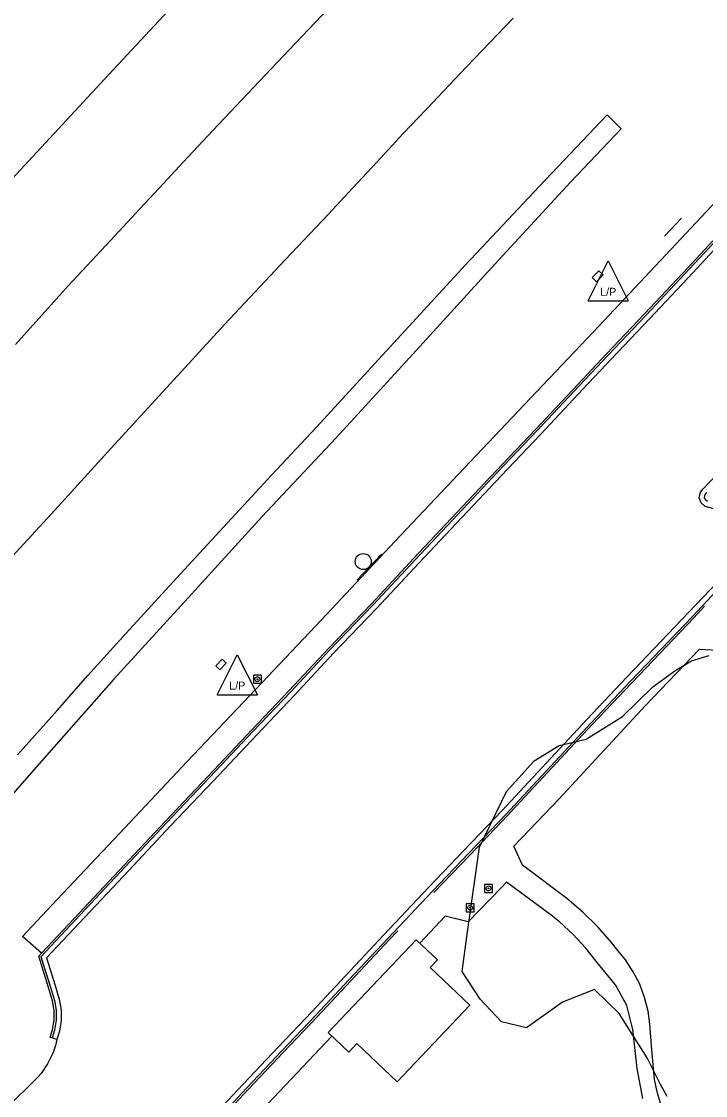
# Model space of a CAD drawing. Extents: x 2161152 to 2175754, y 602179 to 617749.
# Drawn here: x 2163221.4 to 2163392.2, y 605136.2 to 605404.6 of the extents above; entities that cross this region are included whole.
import ezdxf

# ---------------------------------------------------------------- set-up
doc = ezdxf.new("R2010")
doc.units = 0
for name, color, linetype in [('RD_EX_Bldg', 7, 'Continuous'), ('RD_EX_BldgApp_Sign', 7, 'Continuous'), ('RD_EX_Conc_Curb', 7, 'Continuous'), ('RD_EX_Conc_Gutter', 7, 'Continuous'), ('RD_EX_Conc_Sidewalk', 7, 'Continuous'), ('RD_EX_DR_Paved_Drainage', 7, 'Continuous'), ('RD_EX_Fence_Other', 7, 'Continuous'), ('RD_EX_Misc', 7, 'Continuous'), ('RD_EX_Parking_Conc', 7, 'Continuous'), ('RD_EX_Road', 7, 'Continuous'), ('RD_EX_UT', 7, 'Continuous'), ('RD_EX_VEG', 7, 'Continuous')]:
    doc.layers.add(name, color=color, linetype=linetype)

msp = doc.modelspace()

# ---------------------------------------------------------------- linework, layer by layer
at = {"layer": 'RD_EX_Bldg'}
msp.add_lwpolyline([(2163297.98, 605151.89), (2163319.97, 605175.07), (2163325.25, 605170.05), (2163323.43, 605168.13), (2163333.36, 605158.71), (2163315.2, 605139.58), (2163305.14, 605149.12), (2163303.13, 605147), (2163297.98, 605151.89)], dxfattribs=at)
at = {"layer": 'RD_EX_BldgApp_Sign'}
for p, q in [((2163381.98, 605350.93), (2163386.24, 605355.48)), ((2163305.09, 605264.94), (2163311.27, 605271.48))]:
    msp.add_line(p, q, dxfattribs=at)
msp.add_circle((2163306.72, 605269.61), 2, dxfattribs=at)
at = {"layer": 'RD_EX_Conc_Curb'}
for points in [[(2163229.01, 605150.55), (2163228.87, 605150.59), (2163228.53, 605150.69), (2163229.12, 605152.63), (2163229.49, 605155.02), (2163229.48, 605157.44), (2163229.09, 605159.83), (2163228.09, 605163.12), (2163225.64, 605170.99), (2163226.34, 605171.74), (2163234.47, 605180.44), (2163246.88, 605193.63), (2163257.31, 605204.74), (2163267.94, 605215.95), (2163278.89, 605227.55), (2163288.25, 605237.42), (2163298.02, 605247.88), (2163308.77, 605259.08), (2163319.33, 605270.43), (2163328.67, 605280.34), (2163339.88, 605292.28), (2163349.8, 605302.68), (2163360.29, 605313.86), (2163367.5, 605321.55), (2163376.98, 605331.51), (2163387.79, 605343), (2163394.05, 605349.81)], [(2163394.42, 605349.47), (2163388.16, 605342.66), (2163377.34, 605331.17), (2163367.87, 605321.21), (2163360.66, 605313.52), (2163350.16, 605302.34), (2163340.24, 605291.93), (2163329.03, 605280), (2163319.7, 605270.09), (2163309.13, 605258.73), (2163298.39, 605247.53), (2163288.61, 605237.08), (2163279.25, 605227.21), (2163268.3, 605215.61), (2163257.67, 605204.4), (2163247.24, 605193.29), (2163234.83, 605180.1), (2163226.21, 605170.86), (2163228.57, 605163.26), (2163229.58, 605159.94), (2163229.98, 605157.48), (2163229.99, 605154.98), (2163229.61, 605152.51), (2163229.01, 605150.55)], [(2163392.72, 605284.6), (2163392.19, 605285.04), (2163391.98, 605285.64), (2163392.12, 605286.38), (2163392.55, 605286.9)], [(2163269.71, 605129.54), (2163277.67, 605138.1), (2163286.4, 605147.32), (2163294.81, 605156.16), (2163304.38, 605166.38), (2163312.86, 605175.37), (2163324.02, 605187.24), (2163333.02, 605196.63), (2163342.29, 605206.39), (2163363.57, 605229.26), (2163373.5, 605239.75), (2163388.92, 605255.92), (2163396.02, 605263.49)], [(2163324.38, 605186.89), (2163333.38, 605196.29), (2163342.66, 605206.05), (2163363.93, 605228.92), (2163373.86, 605239.41), (2163389.28, 605255.57), (2163391.91, 605258.49)], [(2163315.38, 605177.34), (2163313.22, 605175.03), (2163304.74, 605166.04), (2163295.17, 605155.82), (2163286.76, 605146.98), (2163278.03, 605137.76), (2163269.88, 605128.99)]]:
    msp.add_lwpolyline(points, dxfattribs=at)
at = {"layer": 'RD_EX_Conc_Gutter'}
for points in [[(2163395.33, 605348.62), (2163389.07, 605341.81), (2163378.25, 605330.31), (2163368.77, 605320.35), (2163361.57, 605312.67), (2163351.07, 605301.48), (2163341.15, 605291.08), (2163329.94, 605279.15), (2163320.61, 605269.24), (2163310.04, 605257.88), (2163299.29, 605246.68), (2163289.52, 605236.22), (2163280.16, 605226.35), (2163269.21, 605214.75), (2163258.58, 605203.54), (2163248.15, 605192.44), (2163235.74, 605179.24), (2163227.61, 605170.54), (2163229.76, 605163.63), (2163230.8, 605160.22), (2163231.23, 605157.58), (2163231.24, 605154.89), (2163230.83, 605152.23), (2163230.2, 605150.18), (2163229.01, 605150.55)], [(2163395.86, 605282.4), (2163392.11, 605283.42), (2163391.08, 605284.27), (2163390.64, 605285.55), (2163390.91, 605286.95), (2163391.59, 605287.76), (2163395.27, 605291.63)], [(2163269.26, 605131), (2163276.7, 605139.01), (2163285.44, 605148.23), (2163293.85, 605157.07), (2163303.41, 605167.29), (2163311.89, 605176.28), (2163323.04, 605188.18), (2163332.04, 605197.57), (2163341.31, 605207.32), (2163362.58, 605230.18), (2163372.52, 605240.69), (2163387.94, 605256.85), (2163395.08, 605264.38)]]:
    msp.add_lwpolyline(points, dxfattribs=at)
at = {"layer": 'RD_EX_Conc_Sidewalk'}
for points in [[(2163226.34, 605171.74), (2163221.57, 605175.92), (2163230.15, 605185.03), (2163245.81, 605201.68), (2163262.77, 605219.63), (2163278.37, 605236.12), (2163296.31, 605255.09), (2163314.63, 605274.67), (2163331.93, 605292.95), (2163348.43, 605310.39), (2163364.19, 605327.05), (2163383.51, 605347.58), (2163401.3, 605366.52), (2163420.93, 605387.17), (2163438.78, 605406.02)], [(2163381.24, 605133.39), (2163380.18, 605136.72), (2163379.49, 605140.15), (2163378.77, 605147.55), (2163378.29, 605154.02), (2163377.84, 605157.24), (2163376.99, 605160.66), (2163375.76, 605163.96), (2163374.16, 605167.11), (2163372.23, 605170.07), (2163369.97, 605172.79), (2163368.71, 605174.39), (2163365.27, 605178.31), (2163361.54, 605181.97), (2163357.54, 605185.36), (2163346.47, 605193.74), (2163344.31, 605198.49), (2163355.61, 605210.33), (2163377.14, 605233.53), (2163390.72, 605247.73), (2163396.8, 605247.38)], [(2163376.58, 605135.41), (2163375.17, 605142.89), (2163374.08, 605152.67), (2163372.57, 605158.66), (2163369.74, 605163.81), (2163365.14, 605169.37), (2163362.27, 605173.02), (2163359.13, 605176.43), (2163355.73, 605179.56), (2163353.67, 605181.23), (2163342.51, 605189.48), (2163341.24, 605188.17), (2163332.9, 605179.55), (2163327.15, 605180.95), (2163320.84, 605174.25)], [(2163298.9, 605151.01), (2163282.84, 605134.04)]]:
    msp.add_lwpolyline(points, dxfattribs=at)
at = {"layer": 'RD_EX_DR_Paved_Drainage'}
msp.add_lwpolyline([(2163220.36, 605221.3), (2163230.27, 605232.43), (2163237.96, 605241.17), (2163247.47, 605251.68), (2163259.14, 605264.44), (2163268.82, 605274.98), (2163283.92, 605291.33), (2163294.95, 605303.12), (2163312.4, 605322.22), (2163332.22, 605343.79), (2163350.7, 605363.42), (2163367.62, 605381.24), (2163368.71, 605380.19), (2163370.25, 605378.69), (2163371.17, 605377.81), (2163358.45, 605364.42), (2163339.57, 605343.99), (2163319.12, 605321.49), (2163299.87, 605300.45), (2163281.4, 605280.78), (2163262.95, 605260.57), (2163244.3, 605240.14), (2163223.87, 605216.86), (2163207.2, 605197.86)], dxfattribs=at)
at = {"layer": 'RD_EX_Fence_Other'}
msp.add_lwpolyline([(2162830.61, 604913.75), (2162883.17, 604978.53), (2162926.54, 605031.32), (2162974.34, 605088.61), (2163021.45, 605143.76), (2163066.11, 605195.56), (2163102.29, 605236.75), (2163137.02, 605275.59), (2163187.19, 605331.07), (2163243.16, 605391.37), (2163280.76, 605431.81), (2163328.44, 605482.21), (2163377.08, 605532.2), (2163426.27, 605582.33), (2163479.54, 605635.86), (2163514.27, 605670.47), (2163555.22, 605709.95), (2163593.34, 605746.66), (2163631.88, 605783.63), (2163692.53, 605840.5), (2163757.89, 605901.36), (2163814.91, 605953.51), (2163878.64, 606012.27)], dxfattribs=at)
at = {"layer": 'RD_EX_Misc'}
for points in [[(2163279.27, 605239.2), (2163281.27, 605239.2), (2163281.27, 605241.2), (2163279.27, 605241.2), (2163279.27, 605239.2)], [(2163279.67, 605240.2), (2163279.69, 605240.35), (2163279.74, 605240.5), (2163279.84, 605240.62), (2163279.96, 605240.72), (2163280.1, 605240.78), (2163280.25, 605240.8), (2163280.4, 605240.79), (2163280.54, 605240.73), (2163280.67, 605240.65), (2163280.77, 605240.53), (2163280.84, 605240.39), (2163280.87, 605240.24), (2163280.87, 605240.2)], [(2163280.87, 605240.2), (2163280.85, 605240.05), (2163280.79, 605239.91), (2163280.7, 605239.79), (2163280.58, 605239.69), (2163280.44, 605239.63), (2163280.29, 605239.6), (2163280.13, 605239.62), (2163279.99, 605239.67), (2163279.86, 605239.76), (2163279.76, 605239.88), (2163279.7, 605240.01), (2163279.67, 605240.16), (2163279.67, 605240.2)], [(2163280.17, 605240.2), (2163280.19, 605240.26), (2163280.24, 605240.3), (2163280.3, 605240.3), (2163280.35, 605240.26), (2163280.37, 605240.2)], [(2163280.37, 605240.2), (2163280.35, 605240.14), (2163280.3, 605240.11), (2163280.24, 605240.11), (2163280.19, 605240.14), (2163280.17, 605240.2)], [(2163337, 605186.93), (2163339, 605186.93), (2163339, 605188.93), (2163337, 605188.93), (2163337, 605186.93)], [(2163337.4, 605187.93), (2163337.42, 605188.08), (2163337.48, 605188.23), (2163337.57, 605188.35), (2163337.69, 605188.44), (2163337.83, 605188.51), (2163337.98, 605188.53), (2163338.14, 605188.52), (2163338.28, 605188.46), (2163338.41, 605188.38), (2163338.51, 605188.26), (2163338.57, 605188.12), (2163338.6, 605187.97), (2163338.6, 605187.93)], [(2163338.6, 605187.93), (2163338.58, 605187.78), (2163338.53, 605187.64), (2163338.43, 605187.52), (2163338.31, 605187.42), (2163338.17, 605187.36), (2163338.02, 605187.33), (2163337.87, 605187.35), (2163337.72, 605187.4), (2163337.6, 605187.49), (2163337.5, 605187.61), (2163337.43, 605187.74), (2163337.4, 605187.89), (2163337.4, 605187.93)], [(2163337.9, 605187.93), (2163337.92, 605187.99), (2163337.97, 605188.03), (2163338.03, 605188.03), (2163338.08, 605187.99), (2163338.1, 605187.93)], [(2163338.1, 605187.93), (2163338.08, 605187.87), (2163338.03, 605187.84), (2163337.97, 605187.84), (2163337.92, 605187.87), (2163337.9, 605187.93)], [(2163332.41, 605182.06), (2163334.41, 605182.06), (2163334.41, 605184.06), (2163332.41, 605184.06), (2163332.41, 605182.06)], [(2163332.81, 605183.06), (2163332.83, 605183.21), (2163332.88, 605183.36), (2163332.97, 605183.48), (2163333.09, 605183.57), (2163333.23, 605183.64), (2163333.39, 605183.66), (2163333.54, 605183.65), (2163333.68, 605183.59), (2163333.81, 605183.51), (2163333.91, 605183.39), (2163333.98, 605183.25), (2163334, 605183.1), (2163334.01, 605183.06)], [(2163334.01, 605183.06), (2163333.99, 605182.91), (2163333.93, 605182.77), (2163333.84, 605182.64), (2163333.72, 605182.55), (2163333.58, 605182.49), (2163333.42, 605182.46), (2163333.27, 605182.48), (2163333.13, 605182.53), (2163333, 605182.62), (2163332.9, 605182.73), (2163332.84, 605182.87), (2163332.81, 605183.02), (2163332.81, 605183.06)], [(2163333.31, 605183.06), (2163333.32, 605183.12), (2163333.37, 605183.16), (2163333.44, 605183.16), (2163333.49, 605183.12), (2163333.51, 605183.06)], [(2163333.51, 605183.06), (2163333.49, 605183), (2163333.44, 605182.97), (2163333.37, 605182.97), (2163333.32, 605183), (2163333.31, 605183.06)]]:
    msp.add_lwpolyline(points, dxfattribs=at)
at = {"layer": 'RD_EX_Parking_Conc'}
msp.add_lwpolyline([(2163230.2, 605150.18), (2163229.84, 605148.68), (2163229.32, 605147.17), (2163229.1, 605146.61), (2163227.85, 605144.04), (2163226.26, 605141.68), (2163225.23, 605140.57), (2163223.11, 605138.43), (2163213.14, 605128.74)], dxfattribs=at)
at = {"layer": 'RD_EX_Road'}
for points in [[(2163309.38, 605419.82), (2163288.15, 605397.4), (2163269.03, 605377.3), (2163261.75, 605369.48), (2163255.76, 605362.97), (2163251.99, 605358.95), (2163243.57, 605349.89), (2163233.03, 605338.55), (2163227.91, 605332.84), (2163219.82, 605323.91)], [(2163216.15, 605267.77), (2163229.65, 605282.45), (2163243.7, 605297.87), (2163257.57, 605313.08), (2163272.09, 605328.83), (2163287.27, 605345.13), (2163297.91, 605356.34), (2163304.13, 605363.06), (2163310.07, 605369.43), (2163316.71, 605376.58), (2163322.48, 605382.72), (2163332.54, 605393.28), (2163344.18, 605405.46)]]:
    msp.add_lwpolyline(points, dxfattribs=at)
at = {"layer": 'RD_EX_UT'}
for p, q in [((2163362.9, 605334.76), (2163367.9, 605344.76)), ((2163367.9, 605344.76), (2163372.9, 605334.76)), ((2163362.9, 605334.76), (2163372.9, 605334.76)), ((2163270.26, 605236.33), (2163275.26, 605246.33)), ((2163275.26, 605246.33), (2163280.26, 605236.33)), ((2163270.26, 605236.33), (2163280.26, 605236.33))]:
    msp.add_line(p, q, dxfattribs=at)
for points in [[(2163363.87, 605340.6), (2163364.94, 605339.54), (2163366.64, 605341.27), (2163365.56, 605342.32), (2163363.87, 605340.6)], [(2163269.87, 605243.56), (2163270.87, 605242.57), (2163272.51, 605244.22), (2163271.51, 605245.21), (2163269.87, 605243.56)]]:
    msp.add_lwpolyline(points, dxfattribs=at)
at = {"layer": 'RD_EX_VEG'}
msp.add_lwpolyline([(2163382.59, 605135.88), (2163380.96, 605138.88), (2163377.64, 605145.59), (2163370.65, 605156.67), (2163364.46, 605162.69), (2163356.45, 605159.48), (2163347.46, 605153.11), (2163341.21, 605154.6), (2163335.93, 605160.22), (2163331.46, 605167.19), (2163332.66, 605176.46), (2163335.71, 605198.2), (2163342.52, 605212.14), (2163349.4, 605219.82), (2163355.67, 605223.63), (2163362.37, 605225.23), (2163371.5, 605230.92), (2163379.08, 605238.34), (2163384.5, 605242.33), (2163388.7, 605244.79), (2163393.12, 605246.11)], dxfattribs=at)

# ---------------------------------------------------------------- texts
at = {"layer": 'RD_EX_UT'}
for p in [(2163365.9, 605336.04), (2163273.25, 605237.62)]:
    msp.add_text('L/P', height=2, dxfattribs=at).set_placement(p)

doc.saveas('drawing.dxf')
